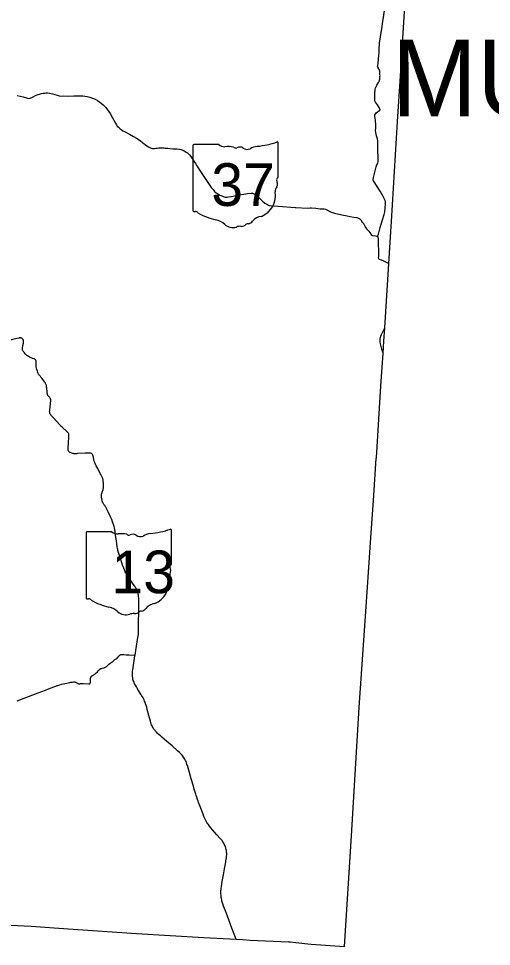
# Model space of a CAD drawing. Extents: x 1761803 to 2441803, y 509895 to 949895.
# Drawn here: x 2076996 to 2107842, y 659945 to 720477 of the extents above; entities that cross this region are included whole.
import ezdxf

# ---------------------------------------------------------------- set-up
doc = ezdxf.new("R2010")
doc.units = 0
for name, color, linetype in [('GM_X_County', 7, 'Continuous'), ('GM_X_Interstate_Location', 7, 'Continuous'), ('GM_X_Minor_Lake', 7, 'Continuous'), ('GM_X_Township_Road', 7, 'Continuous')]:
    doc.layers.add(name, color=color, linetype=linetype)

msp = doc.modelspace()

# ---------------------------------------------------------------- linework, layer by layer
at = {"layer": 'GM_X_County'}
msp.add_lwpolyline([(2075563, 661386), (2077810, 661261), (2080226, 661097), (2084679, 660797), (2089085, 660519), (2091196, 660419), (2091602, 660391), (2092097, 660365), (2093595, 660292), (2094597, 660237), (2094720, 660243), (2095093, 660203), (2095875, 660123), (2096076, 660103), (2098251, 659945), (2098708, 667167), (2099215, 675528), (2099682, 682427), (2099989, 686922), (2100148, 689034), (2100328, 691767), (2100345, 691813), (2100632, 696506), (2100777, 698645), (2100817, 699425), (2100882, 700291), (2101138, 704501), (2101292, 706905), (2101312, 707234), (2101722, 713760), (2101907, 716726), (2102194, 721282)], dxfattribs=at)
at = {"layer": 'GM_X_Minor_Lake'}
for points in [[(2100572, 716815), (2100571, 716851), (2100568, 716979), (2100564, 717050), (2100492, 717189), (2100433, 717306), (2100418, 717362), (2100421, 717417), (2100438, 717470), (2100450, 717524), (2100481, 717839), (2100512, 718284), (2100512, 718462), (2100543, 718875), (2100669, 719702), (2100686, 719812), (2100760, 720292), (2100818, 720708), (2100851, 720884), (2100904, 721052), (2101021, 721309), (2101081, 721479), (2101080, 721504)], [(2100227, 715261), (2100227, 715264), (2100229, 715349), (2100237, 715530), (2100238, 715563), (2100243, 715639), (2100243, 715701), (2100248, 715763), (2100256, 715821), (2100264, 715861), (2100289, 715950), (2100298, 715979), (2100310, 716008), (2100324, 716040), (2100336, 716063), (2100346, 716082), (2100374, 716129), (2100438, 716236), (2100484, 716313), (2100499, 716347), (2100508, 716372), (2100524, 716411), (2100538, 716450), (2100548, 716475), (2100552, 716492), (2100557, 716524), (2100560, 716544), (2100562, 716562), (2100566, 716601), (2100569, 716651), (2100569, 716699), (2100573, 716771), (2100572, 716815)], [(2076905, 715455), (2077288, 715364), (2077515, 715296), (2077642, 715269), (2077753, 715291), (2077909, 715357), (2078147, 715469), (2078273, 715521), (2078366, 715547), (2078484, 715578), (2078603, 715603), (2078680, 715616), (2078779, 715623), (2078881, 715629), (2079020, 715610), (2079218, 715557), (2079506, 715472), (2079645, 715439), (2079802, 715424), (2079930, 715429), (2080192, 715424), (2080611, 715429), (2081184, 715426), (2081339, 715416), (2081467, 715395), (2081655, 715348), (2081820, 715294), (2081983, 715218), (2082144, 715127), (2082303, 715015), (2082386, 714951), (2082507, 714846), (2082687, 714673), (2082800, 714525), (2082962, 714281), (2083127, 714000), (2083319, 713658), (2083391, 713546), (2083436, 713460), (2083510, 713381), (2083623, 713280), (2083685, 713234), (2083804, 713149), (2083913, 713101), (2084240, 712933), (2084498, 712787), (2084690, 712670), (2084918, 712518), (2085079, 712400), (2085358, 712183), (2085473, 712108), (2085635, 712031), (2085729, 712008), (2085791, 711997), (2085868, 712001), (2085947, 712014), (2086028, 712029), (2086118, 712044), (2086225, 712046), (2086361, 712042), (2086466, 712036), (2086569, 712023), (2086729, 712014), (2086868, 712004), (2087055, 711986), (2087343, 711974), (2087487, 711956), (2087587, 711931), (2087716, 711884), (2087799, 711846), (2087932, 711766), (2088007, 711719), (2088056, 711682), (2088144, 711595), (2088233, 711475), (2088306, 711362), (2088361, 711288), (2088419, 711180), (2088530, 711016), (2088616, 710868), (2088867, 710492), (2089334, 709788), (2089560, 709463), (2089691, 709315), (2089785, 709205), (2089895, 709108), (2089973, 709054), (2090034, 709014), (2090132, 708963), (2090258, 708903), (2090397, 708852), (2090496, 708835), (2090612, 708831), (2090693, 708839), (2090883, 708877), (2091271, 708957), (2091814, 709053)], [(2100408, 706276), (2100464, 706414), (2100522, 706579), (2100591, 706844), (2100652, 707054), (2100742, 707343), (2100851, 707691), (2100894, 707858), (2100934, 708401), (2100932, 708525), (2100914, 708602), (2100870, 708699), (2100765, 708917), (2100585, 709226), (2100150, 709888), (2100131, 709961), (2100158, 710103), (2100330, 710799), (2100339, 710853), (2100350, 710895), (2100407, 711002), (2100438, 711062), (2100460, 711142), (2100427, 712136), (2100421, 712330), (2100428, 712496), (2100415, 712625), (2100354, 712832), (2100302, 713054), (2100274, 713180), (2100298, 713326), (2100309, 713521), (2100282, 713858), (2100241, 714116), (2100244, 714190), (2100271, 714254), (2100323, 714321), (2100558, 714494), (2100573, 714505), (2100586, 714514), (2100524, 714673), (2100407, 714847), (2100336, 714933), (2100281, 715014), (2100242, 715104), (2100237, 715123), (2100232, 715154), (2100228, 715186), (2100227, 715219), (2100227, 715261)], [(2091814, 709053), (2091935, 709074), (2092147, 709091), (2092257, 709093), (2092407, 709019), (2092552, 708916), (2092757, 708724), (2092892, 708584), (2093069, 708433), (2093147, 708380), (2093234, 708338), (2093291, 708301), (2093344, 708282)], [(2093344, 708282), (2093921, 708233), (2095034, 708160)], [(2095034, 708160), (2095087, 708157), (2095851, 708117), (2096017, 708132), (2096109, 708128), (2096378, 708103), (2096525, 708096), (2096675, 708073), (2096929, 708058), (2097023, 708035), (2097154, 707983), (2097348, 707871), (2097595, 707783), (2098082, 707674), (2098421, 707602), (2098618, 707563), (2098871, 707516), (2099060, 707491), (2099171, 707457), (2099254, 707416), (2099326, 707338), (2099417, 707202), (2099470, 707148), (2099507, 707108), (2099565, 706968), (2099638, 706820), (2099691, 706762), (2099778, 706682), (2099849, 706607), (2099902, 706527), (2100011, 706349), (2100089, 706326), (2100275, 706300), (2100361, 706290), (2100408, 706276)], [(2100408, 706276), (2100432, 706248), (2100439, 706215), (2100444, 706101), (2100460, 705757), (2100484, 705316), (2100478, 705176), (2100465, 704961), (2100458, 704858), (2100465, 704825), (2100485, 704797), (2100525, 704772), (2100578, 704761), (2100755, 704696), (2101138, 704501)], [(2100777, 698645), (2100702, 698918), (2100646, 699087), (2100602, 699252), (2100580, 699393), (2100579, 699512), (2100581, 699585), (2100597, 699681), (2100628, 699766), (2100667, 699862), (2100719, 699962), (2100882, 700291)], [(2077066, 699646), (2077064, 699646), (2077036, 699642), (2077005, 699636), (2076880, 699605), (2076624, 699537), (2076289, 699453), (2076053, 699390), (2075528, 699259), (2075215, 699188), (2075071, 699158), (2074990, 699138), (2074918, 699121), (2074844, 699101), (2074794, 699085)], [(2083295, 686995), (2083275, 687139), (2083257, 687245), (2083231, 687345), (2083211, 687409), (2083189, 687470), (2083131, 687639), (2083076, 687795), (2083043, 687874), (2083003, 687964), (2082847, 688291), (2082763, 688470), (2082743, 688509), (2082727, 688543), (2082703, 688588), (2082675, 688630), (2082636, 688685), (2082597, 688733), (2082565, 688778), (2082542, 688814), (2082520, 688853), (2082499, 688895), (2082474, 688950), (2082454, 689011), (2082443, 689051), (2082426, 689140), (2082409, 689264), (2082403, 689324), (2082399, 689369), (2082402, 689411), (2082405, 689439), (2082411, 689473), (2082418, 689503), (2082466, 689642), (2082487, 689695), (2082505, 689746), (2082523, 689801), (2082536, 689851), (2082544, 689899), (2082547, 689948), (2082532, 690164), (2082522, 690270), (2082517, 690334), (2082510, 690386), (2082502, 690429), (2082491, 690466), (2082477, 690509), (2082459, 690551), (2082430, 690610), (2082365, 690733), (2082329, 690804), (2082158, 691129), (2082067, 691304), (2081997, 691444), (2081973, 691491), (2081961, 691517), (2081945, 691559), (2081931, 691607), (2081911, 691694), (2081886, 691843), (2081877, 691884), (2081870, 691911), (2081859, 691946), (2081846, 691977), (2081835, 692003), (2081817, 692035), (2081806, 692053), (2081789, 692075), (2081771, 692091), (2081750, 692107), (2081723, 692121), (2081701, 692128), (2081677, 692132), (2081645, 692133), (2081573, 692131), (2081347, 692120), (2080851, 692095), (2080769, 692091), (2080708, 692088), (2080676, 692087), (2080640, 692086), (2080607, 692089), (2080572, 692095), (2080531, 692103), (2080478, 692120), (2080368, 692162), (2080335, 692178), (2080315, 692189), (2080288, 692212), (2080266, 692238), (2080249, 692269), (2080238, 692305), (2080234, 692330), (2080232, 692361), (2080242, 692524), (2080256, 692762), (2080283, 693208), (2080284, 693283), (2080279, 693340), (2080274, 693368), (2080266, 693395), (2080252, 693426), (2080236, 693452), (2080215, 693478), (2080190, 693503), (2080127, 693561), (2079852, 693804), (2079762, 693889), (2079721, 693931), (2079668, 693988), (2079492, 694187), (2079273, 694429), (2079164, 694549), (2079133, 694581), (2079115, 694602), (2079094, 694628), (2079075, 694656), (2079055, 694689), (2079041, 694723), (2079033, 694747), (2079026, 694777), (2079022, 694817), (2079022, 694850), (2079025, 694894), (2079032, 694963), (2079050, 695132), (2079075, 695367), (2079093, 695563), (2079093, 695599), (2079091, 695624), (2079086, 695652), (2079078, 695676), (2079065, 695702), (2079045, 695732), (2079013, 695770), (2078932, 695861), (2078922, 695874), (2078911, 695888), (2078900, 695906), (2078891, 695926), (2078881, 695952), (2078873, 695982), (2078865, 696034), (2078853, 696153), (2078836, 696357), (2078829, 696436), (2078824, 696470), (2078818, 696506), (2078810, 696548), (2078801, 696576), (2078790, 696607), (2078777, 696636), (2078761, 696668), (2078726, 696726), (2078690, 696776), (2078579, 696927), (2078516, 697010), (2078494, 697037), (2078473, 697063), (2078450, 697091), (2078425, 697121), (2078400, 697150), (2078373, 697183), (2078344, 697218), (2078318, 697251), (2078299, 697282), (2078276, 697326), (2078254, 697385), (2078227, 697469), (2078192, 697582), (2078168, 697667), (2078154, 697722), (2078146, 697760), (2078139, 697818), (2078137, 697885), (2078140, 698000), (2078142, 698045), (2078143, 698076), (2078142, 698098), (2078138, 698124), (2078134, 698142), (2078126, 698169), (2078114, 698195), (2078097, 698222), (2078077, 698241), (2078055, 698258), (2078033, 698270), (2078013, 698279), (2077985, 698288), (2077939, 698300), (2077899, 698310), (2077861, 698322), (2077812, 698344), (2077754, 698375), (2077702, 698403), (2077642, 698439), (2077582, 698474), (2077537, 698502), (2077503, 698527), (2077465, 698559), (2077425, 698599), (2077377, 698660), (2077333, 698720), (2077312, 698751), (2077291, 698782), (2077276, 698811), (2077263, 698844), (2077254, 698875), (2077248, 698912), (2077249, 698956), (2077258, 699018), (2077274, 699101), (2077284, 699151), (2077316, 699306), (2077325, 699359), (2077328, 699392), (2077328, 699413), (2077324, 699443), (2077320, 699466), (2077312, 699491), (2077302, 699515), (2077290, 699536), (2077275, 699557), (2077258, 699578), (2077247, 699590), (2077226, 699604), (2077201, 699619), (2077176, 699630), (2077152, 699639), (2077118, 699645), (2077087, 699647), (2077066, 699646)], [(2083302, 686945), (2083299, 686972), (2083295, 686995)], [(2084613, 683384), (2084551, 683480), (2084479, 683585), (2084317, 683821), (2084218, 683968), (2084094, 684144), (2084038, 684231), (2083993, 684308), (2083950, 684390), (2083924, 684447), (2083898, 684506), (2083858, 684612), (2083815, 684733), (2083785, 684825), (2083670, 685180), (2083539, 685581), (2083518, 685649), (2083482, 685777), (2083463, 685858), (2083457, 685893), (2083433, 686023), (2083377, 686410), (2083348, 686616), (2083302, 686945)], [(2084836, 681929), (2084837, 682191), (2084841, 682479), (2084841, 682586), (2084837, 682678), (2084829, 682773), (2084818, 682851), (2084818, 682856), (2084801, 682932), (2084780, 683014), (2084753, 683098), (2084728, 683159), (2084714, 683192), (2084663, 683297), (2084615, 683381), (2084613, 683384)], [(2084598, 678939), (2084650, 679242), (2084738, 679806), (2084785, 680096), (2084809, 680286), (2084821, 680531), (2084826, 680916), (2084830, 681339), (2084834, 681509), (2084836, 681915), (2084836, 681929)], [(2082971, 678412), (2083037, 678461), (2083092, 678503), (2083137, 678539), (2083186, 678583), (2083187, 678584), (2083214, 678606), (2083243, 678629), (2083258, 678641)], [(2083258, 678641), (2083279, 678656), (2083328, 678689), (2083371, 678717), (2083402, 678740), (2083418, 678754), (2083434, 678771), (2083449, 678788), (2083462, 678803), (2083534, 678889), (2083563, 678917), (2083585, 678935), (2083609, 678955), (2083629, 678969), (2083641, 678978), (2083656, 678985), (2083671, 678989), (2083695, 678993), (2083720, 678994), (2083864, 678988), (2084008, 678977)], [(2084008, 678977), (2084215, 678962), (2084598, 678939)], [(2085002, 676348), (2084970, 676400), (2084887, 676537), (2084726, 676799), (2084680, 676871), (2084619, 676982), (2084566, 677083), (2084539, 677139), (2084527, 677173), (2084505, 677229), (2084481, 677304), (2084457, 677396), (2084441, 677483), (2084433, 677543), (2084428, 677589), (2084423, 677662), (2084423, 677765), (2084428, 677836), (2084436, 677904), (2084447, 677996), (2084497, 678300), (2084591, 678900), (2084598, 678939)], [(2076914, 675972), (2077525, 676205), (2077923, 676361), (2078266, 676489), (2078759, 676674), (2078945, 676745), (2079307, 676884), (2079427, 676931), (2079506, 676960), (2079557, 676979), (2079618, 676999), (2079687, 677019), (2079799, 677050), (2080012, 677102), (2080140, 677131), (2080241, 677151), (2080348, 677169), (2080413, 677178), (2080501, 677189), (2080582, 677197), (2080632, 677199), (2080663, 677198), (2080683, 677196), (2080705, 677191), (2080729, 677182), (2080750, 677172), (2080788, 677149), (2080841, 677110), (2080862, 677097), (2080879, 677089), (2080895, 677083), (2080915, 677077), (2080932, 677075), (2080946, 677075), (2080960, 677075), (2080977, 677078), (2080997, 677082), (2081029, 677088), (2081053, 677091), (2081080, 677093), (2081114, 677095), (2081149, 677095), (2081211, 677093), (2081569, 677074), (2081609, 677076), (2081622, 677079), (2081635, 677083), (2081645, 677090), (2081657, 677102), (2081666, 677113), (2081673, 677132), (2081678, 677165), (2081682, 677223), (2081689, 677340), (2081692, 677380), (2081694, 677420), (2081697, 677453), (2081701, 677476), (2081707, 677497), (2081712, 677512), (2081722, 677534), (2081732, 677548), (2081744, 677561), (2081759, 677576), (2081776, 677589), (2081796, 677601), (2081829, 677619), (2081861, 677636), (2081900, 677657), (2081937, 677685), (2081967, 677708), (2082009, 677745), (2082062, 677792), (2082114, 677840), (2082136, 677861), (2082216, 677944), (2082258, 677989), (2082270, 678001), (2082289, 678019), (2082305, 678030), (2082325, 678045), (2082344, 678056), (2082365, 678067), (2082382, 678075), (2082415, 678086), (2082454, 678099), (2082532, 678120), (2082556, 678128), (2082592, 678140), (2082625, 678152), (2082659, 678169), (2082695, 678192), (2082751, 678236), (2082818, 678290), (2082868, 678330), (2082959, 678403), (2082971, 678412)], [(2091196, 660419), (2091058, 660754), (2090910, 661146), (2090799, 661441), (2090624, 661911), (2090489, 662261), (2090372, 662575), (2090317, 662732), (2090286, 662828), (2090266, 662907), (2090248, 662988), (2090233, 663067), (2090220, 663141), (2090212, 663208), (2090204, 663290), (2090199, 663373), (2090196, 663434), (2090199, 663533), (2090201, 663595), (2090206, 663661), (2090212, 663732), (2090230, 663852), (2090287, 664192), (2090364, 664620), (2090432, 665011), (2090490, 665345), (2090543, 665656), (2090555, 665736), (2090565, 665826), (2090572, 665917), (2090572, 666019), (2090564, 666127), (2090555, 666199), (2090539, 666276), (2090519, 666355), (2090486, 666464), (2090465, 666515), (2090439, 666572), (2090405, 666641), (2090365, 666709), (2090337, 666753), (2090296, 666815), (2090268, 666853), (2090235, 666896), (2090157, 666987), (2089939, 667234), (2089647, 667560), (2089532, 667690), (2089447, 667796), (2089376, 667890), (2089334, 667951), (2089284, 668033), (2089241, 668108), (2089194, 668200), (2089150, 668294), (2089092, 668432), (2089039, 668567), (2088834, 669076), (2088733, 669344), (2088701, 669424), (2088663, 669528), (2088616, 669676), (2088583, 669782), (2088555, 669877), (2088461, 670201), (2088399, 670409), (2088259, 670889), (2088140, 671296), (2088006, 671748), (2087983, 671824), (2087950, 671922), (2087919, 672003), (2087891, 672066), (2087847, 672153), (2087809, 672219), (2087762, 672291), (2087713, 672363), (2087666, 672421), (2087625, 672471), (2087580, 672519), (2087494, 672602), (2087370, 672714), (2087006, 673028), (2086644, 673340), (2086346, 673599), (2086249, 673684), (2086162, 673758), (2086065, 673845), (2085987, 673921), (2085924, 673992), (2085896, 674024), (2085862, 674068), (2085818, 674130), (2085774, 674201), (2085740, 674261), (2085706, 674329), (2085671, 674411), (2085650, 674467), (2085625, 674547), (2085599, 674633), (2085500, 675005), (2085395, 675400), (2085358, 675546), (2085286, 675783), (2085251, 675875), (2085216, 675956), (2085184, 676026), (2085157, 676080), (2085116, 676156), (2085032, 676299), (2085002, 676348)]]:
    msp.add_lwpolyline(points, dxfattribs=at)
at = {"layer": 'GM_X_Township_Road'}
for p, q in [((2088368, 712181), (2088368, 707955)), ((2090054, 712254), (2088423, 712254)), ((2093937, 710148), (2093937, 712359)), ((2093936, 710148), (2093937, 710148)), ((2086968, 684884), (2086968, 687095)), ((2081399, 686918), (2081399, 682691)), ((2083085, 686990), (2081454, 686990)), ((2086967, 684885), (2086968, 684884))]:
    msp.add_line(p, q, dxfattribs=at)
for centre, radius, start, end in [((2088432, 712190), 64.5, 98.1301, 188.1301), ((2090442, 712744), 626, 231.61951, 271.11188), ((2090650, 709881), 2246, 80.48669, 94.98827), ((2091160, 712212), 181, 219.79206, 297.10237), ((2091425, 711723), 375, 54.46668, 119.14113), ((2091909, 712394), 452, 233.85621, 294.82819), ((2092706, 710963), 1188, 97.34618, 120.76885), ((2091953, 718016), 5905, 275.84447, 288.90645), ((2093875, 712368), 62, 351.86209, 97.738), ((2093922, 709985), 95.9, 107.94398, 210.33697), ((2093871, 710139), 66.3, 289.60381, 7.73413), ((2094159, 709222), 419, 136.8065, 186.92959), ((2093312, 709706), 576, 340.03296, 23.64957), ((2092284, 708941), 1477, 292.30889, 8.98584), ((2088432, 707945), 65.1, 171.95839, 258.30661), ((2088442, 708378), 497, 267.33899, 280.60386), ((2088544, 707711), 179, 29.74838, 93.27175), ((2090805, 711508), 4265, 240.41292, 257.1985), ((2089534, 706056), 1334, 47.18416, 75.83597), ((2090977, 707690), 847, 230.70037, 286.29184), ((2091528, 707373), 451, 268.77702, 315.54927), ((2091936, 706964), 127, 65.75173, 132.64842), ((2091882, 707545), 477, 282.87319, 323.27711), ((2092907, 706768), 809, 94.40312, 142.57675), ((2091466, 706228), 696, 85.69512, 111.20995), ((2084984, 692753), 5905, 275.84447, 288.90645), ((2086906, 687104), 62, 351.86209, 97.738), ((2081463, 686927), 64.5, 98.1301, 188.1301), ((2083473, 687481), 626, 231.61951, 271.11188), ((2083681, 684618), 2246, 80.48669, 94.98827), ((2084190, 686949), 181, 219.79206, 297.10237), ((2084456, 686460), 375, 54.46668, 119.14113), ((2084940, 687130), 452, 233.85621, 294.82819), ((2085737, 685699), 1188, 97.34618, 120.76885), ((2086953, 684722), 95.9, 107.94398, 210.33697), ((2086343, 684442), 576, 340.03296, 23.64957), ((2086902, 684876), 66.3, 289.60381, 7.73413), ((2087190, 683959), 419, 136.8065, 186.92959), ((2085315, 683678), 1477, 292.30889, 8.98584), ((2081463, 682682), 65.1, 171.95839, 258.30661), ((2081473, 683114), 497, 267.33899, 280.60386), ((2081575, 682447), 179, 29.74838, 93.27175), ((2083836, 686245), 4265, 240.41292, 257.1985), ((2085938, 681505), 809, 94.40312, 142.57675), ((2082565, 680792), 1334, 47.18416, 75.83597), ((2084008, 682426), 847, 230.70037, 286.29184), ((2084497, 680965), 696, 85.69512, 111.20995), ((2084559, 682110), 451, 268.77702, 315.54927), ((2084967, 681700), 127, 65.75173, 132.64842), ((2084913, 682281), 477, 282.87319, 323.27711)]:
    msp.add_arc(centre, radius, start, end, dxfattribs=at)

# ---------------------------------------------------------------- texts
at = {"layer": 'GM_X_Interstate_Location'}
msp.add_text('MUSKINGUM', height=5000, dxfattribs=at).set_placement((2101332, 714108))
at = {"layer": 'GM_X_Township_Road'}
for s, p in [('37', (2089570, 708253)), ('13', (2083057, 682989))]:
    msp.add_text(s, height=2784.4, dxfattribs=at).set_placement(p)

doc.saveas('drawing.dxf')
